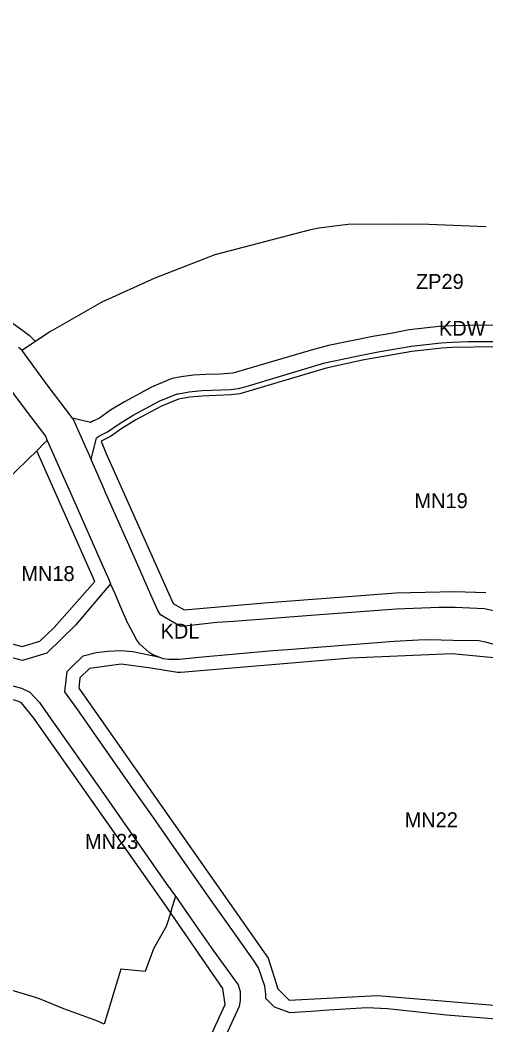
# Model space of a CAD drawing. Extents: x 7428080 to 7432143, y 5545880 to 5549217.
# Drawn here: x 7430556.7 to 7430729.6, y 5547442.4 to 5547815.6 of the extents above; entities that cross this region are included whole.
import ezdxf

# ---------------------------------------------------------------- set-up
doc = ezdxf.new("R2010")
doc.units = 0
for name, color, linetype in [('CZ_L_linie rozgraniczające tereny o różnym przeznaczeniu oraz różnych warunkach ich zabudowy i zagospodarowania', 7, 'Continuous'), ('CZ_L_maksymalne nieprzekraczalne linie zabudowy', 7, 'Continuous'), ('CZ_L_opisy_linie rozgraniczające tereny o różnym przeznaczeniu oraz różnych warunkach ich zabudowy i zagospodarowania', 7, 'Continuous')]:
    doc.layers.add(name, color=color, linetype=linetype)

msp = doc.modelspace()

# ---------------------------------------------------------------- linework, layer by layer
at = {"layer": 'CZ_L_linie rozgraniczające tereny o różnym przeznaczeniu oraz różnych warunkach ich zabudowy i zagospodarowania'}
for p, q in [((7430664.02, 5547737.66), (7430629.03, 5547728.4)), ((7430667.58, 5547738.33), (7430664.02, 5547737.66)), ((7430675.38, 5547739.39), (7430667.58, 5547738.33)), ((7430678.46, 5547739.66), (7430675.38, 5547739.39)), ((7430696.08, 5547739.78), (7430678.46, 5547739.66)), ((7430708.44, 5547739.76), (7430696.08, 5547739.78)), ((7430729.73, 5547738.83), (7430708.44, 5547739.76)), ((7430629.03, 5547728.4), (7430606.68, 5547719.72)), ((7430606.68, 5547719.72), (7430587.07, 5547710.86)), ((7430587.07, 5547710.86), (7430567.98, 5547700.01)), ((7430567.98, 5547700.01), (7430558.51, 5547693.61)), ((7430701.15, 5547700.64), (7430693.64, 5547699.16)), ((7430712.19, 5547701.79), (7430701.15, 5547700.64)), ((7430717.26, 5547702.07), (7430712.19, 5547701.79)), ((7430728.1, 5547702.36), (7430717.26, 5547702.07)), ((7430734.35, 5547702.22), (7430728.1, 5547702.36)), ((7430687.59, 5547698.13), (7430671.17, 5547694.74)), ((7430693.64, 5547699.16), (7430687.59, 5547698.13)), ((7430701.8, 5547694.56), (7430713.01, 5547695.79)), ((7430713.01, 5547695.79), (7430717.09, 5547696.05)), ((7430717.09, 5547696.05), (7430723.1, 5547696.2)), ((7430723.1, 5547696.2), (7430726.23, 5547696.23)), ((7430726.23, 5547696.23), (7430733.01, 5547696.31)), ((7430557.44, 5547692.86), (7430556.18, 5547694.04)), ((7430558.52, 5547693.6), (7430557.44, 5547692.86)), ((7430567.19, 5547679.65), (7430557.44, 5547692.86)), ((7430558.51, 5547693.61), (7430558.52, 5547693.6)), ((7430665.6, 5547693.34), (7430635.62, 5547684.47)), ((7430671.17, 5547694.74), (7430665.6, 5547693.34)), ((7430683.37, 5547691.22), (7430689.57, 5547692.38)), ((7430689.57, 5547692.38), (7430701.8, 5547694.56)), ((7430664.82, 5547686.81), (7430669.81, 5547688.31)), ((7430669.81, 5547688.31), (7430683.37, 5547691.22)), ((7430640.58, 5547679.57), (7430664.82, 5547686.81)), ((7430549.72, 5547682.85), (7430560.99, 5547667.96)), ((7430612.2, 5547682.18), (7430605.47, 5547679.32)), ((7430613.21, 5547682.56), (7430612.2, 5547682.18)), ((7430616.54, 5547683.17), (7430613.21, 5547682.56)), ((7430621.03, 5547683.77), (7430616.54, 5547683.17)), ((7430625.69, 5547684.05), (7430621.03, 5547683.77)), ((7430631.14, 5547684.14), (7430625.69, 5547684.05)), ((7430635.62, 5547684.47), (7430631.14, 5547684.14)), ((7430576.16, 5547667.79), (7430567.19, 5547679.65)), ((7430605.47, 5547679.32), (7430595.44, 5547673.89)), ((7430615.52, 5547676.87), (7430619.49, 5547677.59)), ((7430619.49, 5547677.59), (7430624.15, 5547677.99)), ((7430624.15, 5547677.99), (7430634.82, 5547678.38)), ((7430634.82, 5547678.38), (7430637.74, 5547678.78)), ((7430637.74, 5547678.78), (7430640.58, 5547679.57)), ((7430595.44, 5547673.89), (7430590.25, 5547670.7)), ((7430598.66, 5547668.83), (7430608.28, 5547674.07)), ((7430608.28, 5547674.07), (7430612.34, 5547675.72)), ((7430612.34, 5547675.72), (7430614.97, 5547676.77)), ((7430614.97, 5547676.77), (7430615.52, 5547676.87)), ((7430590.25, 5547670.7), (7430586.18, 5547667.81)), ((7430560.99, 5547667.96), (7430566.18, 5547661.03)), ((7430582.88, 5547666.13), (7430576.16, 5547667.79)), ((7430576.16, 5547667.79), (7430576.58, 5547667.17)), ((7430576.58, 5547667.17), (7430578.33, 5547663.2)), ((7430583.45, 5547666.5), (7430582.88, 5547666.13)), ((7430586.18, 5547667.81), (7430583.45, 5547666.5)), ((7430593.43, 5547665.64), (7430598.66, 5547668.83)), ((7430578.33, 5547663.2), (7430580.81, 5547657.57)), ((7430586.18, 5547661.19), (7430589.21, 5547662.64)), ((7430589.21, 5547662.64), (7430593.43, 5547665.64)), ((7430566.18, 5547661.03), (7430566.79, 5547659.49)), ((7430566.79, 5547659.49), (7430569.4, 5547653.71)), ((7430583.08, 5547652.4), (7430585.12, 5547660.48)), ((7430585.12, 5547660.48), (7430586.18, 5547661.19)), ((7430580.81, 5547657.57), (7430583.08, 5547652.4)), ((7430569.4, 5547653.71), (7430576.89, 5547636.69)), ((7430585.18, 5547647.64), (7430583.08, 5547652.4)), ((7430587.94, 5547641.35), (7430585.18, 5547647.64)), ((7430588.34, 5547640.46), (7430587.94, 5547641.35)), ((7430598.05, 5547618.44), (7430588.34, 5547640.46)), ((7430576.89, 5547636.69), (7430586.94, 5547613.89)), ((7430601.38, 5547610.89), (7430598.05, 5547618.44)), ((7430586.94, 5547613.89), (7430589.73, 5547607.56)), ((7430602.63, 5547608.15), (7430601.38, 5547610.89)), ((7430590.32, 5547606.24), (7430577.29, 5547590.83)), ((7430589.73, 5547607.56), (7430590.32, 5547606.24)), ((7430592.09, 5547602.22), (7430590.32, 5547606.24)), ((7430605.69, 5547600.99), (7430602.63, 5547608.15)), ((7430602.63, 5547608.15), (7430602.63, 5547608.15)), ((7430592.1, 5547602.21), (7430592.09, 5547602.22)), ((7430592.85, 5547600.47), (7430592.1, 5547602.21)), ((7430594.77, 5547596.07), (7430592.85, 5547600.47)), ((7430607.9, 5547596.34), (7430605.69, 5547600.99)), ((7430596.72, 5547591.56), (7430594.77, 5547596.07)), ((7430608.8, 5547594.71), (7430607.9, 5547596.34)), ((7430696.39, 5547596.85), (7430668, 5547594.73)), ((7430712.14, 5547597.42), (7430696.39, 5547596.85)), ((7430718.21, 5547597.39), (7430712.14, 5547597.42)), ((7430729.05, 5547596.99), (7430718.21, 5547597.39)), ((7430734.68, 5547595.76), (7430729.05, 5547596.99)), ((7430596.92, 5547591.19), (7430596.72, 5547591.56)), ((7430616.27, 5547590.41), (7430608.8, 5547594.71)), ((7430629.72, 5547591.85), (7430617.7, 5547590.51)), ((7430635.92, 5547592.24), (7430629.72, 5547591.85)), ((7430668, 5547594.73), (7430635.92, 5547592.24)), ((7430577.29, 5547590.83), (7430566.7, 5547580.48)), ((7430596.95, 5547591.14), (7430596.92, 5547591.19)), ((7430598.84, 5547587.61), (7430596.95, 5547591.14)), ((7430600.09, 5547585.29), (7430598.84, 5547587.61)), ((7430617.7, 5547590.51), (7430616.27, 5547590.41)), ((7430601.22, 5547583.78), (7430600.09, 5547585.29)), ((7430604.54, 5547580.81), (7430601.22, 5547583.78)), ((7430655.99, 5547581.82), (7430695.6, 5547584.89)), ((7430695.6, 5547584.89), (7430704.57, 5547585.49)), ((7430704.57, 5547585.49), (7430708.69, 5547585.52)), ((7430708.69, 5547585.52), (7430717.25, 5547585.28)), ((7430717.25, 5547585.28), (7430726.97, 5547585.19)), ((7430726.97, 5547585.19), (7430729.3, 5547584.64)), ((7430729.3, 5547584.64), (7430733.54, 5547583.61)), ((7430566.7, 5547580.48), (7430557.59, 5547577.78)), ((7430580.14, 5547579.53), (7430585.01, 5547580.7)), ((7430585.01, 5547580.7), (7430589.13, 5547581.26)), ((7430589.13, 5547581.26), (7430594.2, 5547581.47)), ((7430594.2, 5547581.47), (7430598.62, 5547581.12)), ((7430598.62, 5547581.12), (7430608.11, 5547579.1)), ((7430605.61, 5547580.11), (7430604.54, 5547580.81)), ((7430605.94, 5547579.89), (7430605.61, 5547580.11)), ((7430623.07, 5547579.03), (7430650.47, 5547581.41)), ((7430650.47, 5547581.41), (7430655.99, 5547581.82)), ((7430557.59, 5547577.78), (7430552.02, 5547579.23)), ((7430575.97, 5547575.35), (7430580.14, 5547579.53)), ((7430608.11, 5547579.1), (7430605.94, 5547579.89)), ((7430608.11, 5547579.1), (7430609.79, 5547578.49)), ((7430609.79, 5547578.49), (7430611.94, 5547578.19)), ((7430611.94, 5547578.19), (7430615.92, 5547578.26)), ((7430615.92, 5547578.26), (7430623.07, 5547579.03)), ((7430573.29, 5547566.14), (7430574.15, 5547573.68)), ((7430574.15, 5547573.68), (7430575.97, 5547575.35)), ((7430541.51, 5547571.64), (7430557.25, 5547567.51)), ((7430557.25, 5547567.51), (7430560.4, 5547566.03)), ((7430560.4, 5547566.03), (7430563.96, 5547562.1)), ((7430578.76, 5547558.52), (7430573.29, 5547566.14)), ((7430563.96, 5547562.1), (7430568.1, 5547556.08)), ((7430583.86, 5547551.21), (7430578.76, 5547558.52)), ((7430568.1, 5547556.08), (7430574.13, 5547547.61)), ((7430598.47, 5547530.36), (7430583.86, 5547551.21)), ((7430574.13, 5547547.61), (7430587.65, 5547528.31)), ((7430587.65, 5547528.31), (7430597.36, 5547514.49)), ((7430606.06, 5547519.55), (7430598.47, 5547530.36)), ((7430617.85, 5547502.54), (7430606.06, 5547519.55)), ((7430597.36, 5547514.49), (7430610.95, 5547494.95)), ((7430627.98, 5547488.08), (7430617.85, 5547502.54)), ((7430610.95, 5547494.95), (7430614.37, 5547490.23)), ((7430614.37, 5547490.23), (7430612.7, 5547484.65)), ((7430614.37, 5547490.23), (7430614.39, 5547490.2)), ((7430614.39, 5547490.2), (7430621.52, 5547479.86)), ((7430635.9, 5547477.02), (7430627.98, 5547488.08)), ((7430612.73, 5547484.62), (7430610.92, 5547478.89)), ((7430612.7, 5547484.65), (7430612.73, 5547484.62)), ((7430621.52, 5547479.86), (7430628.47, 5547469.92)), ((7430610.92, 5547478.89), (7430606.27, 5547470.6)), ((7430643.28, 5547466.41), (7430635.9, 5547477.02)), ((7430606.27, 5547470.6), (7430603.16, 5547462.28)), ((7430628.47, 5547469.92), (7430637.63, 5547457.26)), ((7430645.22, 5547463.63), (7430643.28, 5547466.41)), ((7430594.1, 5547463.09), (7430587.93, 5547442.64)), ((7430603.16, 5547462.28), (7430594.1, 5547463.09)), ((7430647.53, 5547456.74), (7430645.22, 5547463.63)), ((7430637.63, 5547457.26), (7430638.43, 5547454.74)), ((7430562.02, 5547452.69), (7430552.18, 5547455.64)), ((7430638.43, 5547454.74), (7430638.38, 5547451.51)), ((7430647.86, 5547453.76), (7430647.53, 5547456.74)), ((7430647.92, 5547452.18), (7430647.86, 5547453.76)), ((7430562.46, 5547452.55), (7430562.02, 5547452.69)), ((7430563.88, 5547452.12), (7430562.46, 5547452.55)), ((7430573, 5547448.38), (7430563.88, 5547452.12)), ((7430638.38, 5547451.51), (7430638.01, 5547449.24)), ((7430651.09, 5547449), (7430647.92, 5547452.18)), ((7430585.23, 5547443.85), (7430573, 5547448.38)), ((7430638.01, 5547449.24), (7430632.96, 5547438.23)), ((7430656.92, 5547446.84), (7430651.09, 5547449)), ((7430666.41, 5547447.53), (7430656.92, 5547446.84)), ((7430669.28, 5547447.74), (7430666.41, 5547447.53)), ((7430685.35, 5547448.72), (7430669.28, 5547447.74)), ((7430693.03, 5547448.4), (7430685.35, 5547448.72)), ((7430714.93, 5547446.02), (7430693.03, 5547448.4)), ((7430740.06, 5547444.05), (7430714.93, 5547446.02)), ((7430587.93, 5547442.64), (7430585.23, 5547443.85))]:
    msp.add_line(p, q, dxfattribs=at)
msp.add_lwpolyline([(7430566.79, 5547659.49), (7430565.68, 5547658.44), (7430565.66, 5547658.48), (7430563.17, 5547655.93), (7430555.54, 5547648.41), (7430549.91, 5547642.91), (7430535.33, 5547631.2), (7430523.61, 5547620.18), (7430517.27, 5547611.44), (7430510.47, 5547601.09), (7430507.89, 5547593.24), (7430507.83, 5547593.26), (7430507.8, 5547593.17), (7430506.85, 5547590.37)], dxfattribs=at)
at = {"layer": 'CZ_L_maksymalne nieprzekraczalne linie zabudowy'}
for points in [[(7430373.39, 5547818.56), (7430403.54, 5547810.34), (7430418.52, 5547805.95), (7430424.77, 5547802.91), (7430434.82, 5547794.91), (7430437.91, 5547792.01), (7430449.28, 5547780.53), (7430459.17, 5547771.31), (7430461.45, 5547769.38), (7430481.66, 5547754.26), (7430498.13, 5547741.68), (7430521.04, 5547726.94), (7430557.73, 5547700.37), (7430560.25, 5547698.45), (7430562.39, 5547696.25)], [(7430732.9, 5547694.31), (7430717.18, 5547694.05), (7430713.18, 5547693.8), (7430702.09, 5547692.58), (7430683.77, 5547689.26), (7430670.31, 5547686.37), (7430638.21, 5547676.83), (7430634.9, 5547676.38), (7430624.28, 5547675.99), (7430619.75, 5547675.6), (7430615.54, 5547674.84), (7430609.14, 5547672.26), (7430599.66, 5547667.1), (7430594.54, 5547663.97), (7430590.28, 5547660.95), (7430586.87, 5547659.25), (7430588.56, 5547654.84), (7430613.49, 5547598.93), (7430617.63, 5547596.55), (7430647.39, 5547599.14), (7430696.14, 5547602.85), (7430718.07, 5547603.39), (7430729.59, 5547602.97)], [(7430508.56, 5547595.12), (7430516.4, 5547593.55), (7430538.25, 5547588.06), (7430557.51, 5547582.97), (7430564.09, 5547584.92), (7430569.35, 5547590.07), (7430584.45, 5547607.15), (7430562.9, 5547655.66)], [(7430762.36, 5547447.29), (7430763.84, 5547448.54), (7430783.45, 5547543.43), (7430781.33, 5547552.76), (7430761.76, 5547565), (7430744.76, 5547574.59), (7430732.48, 5547578.69), (7430717.1, 5547580.27), (7430679.42, 5547578.62), (7430616.34, 5547573.27), (7430615.14, 5547573.32), (7430605.2, 5547574.95), (7430594.21, 5547576.42), (7430582.49, 5547574.81), (7430578.9, 5547571.26), (7430578.47, 5547567.46), (7430648.83, 5547467.19), (7430652.37, 5547455.77), (7430656.58, 5547451.53), (7430689.39, 5547453.26), (7430762.36, 5547447.29)], [(7430516.8, 5547572.83), (7430507.68, 5547535.14), (7430507.14, 5547534.25), (7430506.38, 5547533.53), (7430505.47, 5547533.04), (7430504.45, 5547532.79), (7430503.15, 5547532.86), (7430498.44, 5547534.17), (7430497.99, 5547531.78), (7430498.12, 5547526.71), (7430499.25, 5547514.97), (7430506.06, 5547467.82), (7430610.64, 5547401.69), (7430632.86, 5547449.99), (7430632.01, 5547455.96), (7430610.29, 5547487.34), (7430561.88, 5547556.31), (7430557.25, 5547561.99), (7430555.54, 5547562.79), (7430516.81, 5547572.86)]]:
    msp.add_lwpolyline(points, dxfattribs=at)

# ---------------------------------------------------------------- texts
at = {"layer": 'CZ_L_opisy_linie rozgraniczające tereny o różnym przeznaczeniu oraz różnych warunkach ich zabudowy i zagospodarowania'}
for s, p in [('ZP29', (7430703.62, 5547715.77)), ('KDW', (7430712.13, 5547698.38)), ('MN19', (7430703.06, 5547634.35)), ('MN18', (7430557.17, 5547607.28)), ('KDL', (7430608.85, 5547585.9)), ('MN22', (7430699.4, 5547515.81)), ('MN23', (7430580.77, 5547507.78))]:
    msp.add_text(s, height=5.549, dxfattribs=at).set_placement(p)

doc.saveas('drawing.dxf')
